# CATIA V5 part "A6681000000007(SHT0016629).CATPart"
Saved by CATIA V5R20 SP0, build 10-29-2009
Part number: A668100000007(SHT0016629)
Source: Unknown
Bounding box of the stored display mesh (mm): x -453 to 31, y 582 to 876, z 0.9 to 38.4
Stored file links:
  E:\杨逍\02-飞秋\冉凡勇\2023-10-08 13_49_22\2D\副驾\宽车副驾底支架\A668100000007（SHT0016629）-A6宽车副司机座椅底支架总成\A6681000000007(SHT0016629).CATPart

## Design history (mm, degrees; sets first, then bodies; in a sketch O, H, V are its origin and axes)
Set1
  Point1: type OnCurve, Support edge [face of Solid1 | face of Solid1], Ratio 0.5
  Plane1: type Normal, Curve edge [face of Solid1 | face of Solid1], RefPoint Point1
Body1 "SHT0016382-A6宽车副司机座椅底支架上板" (main body)
  Solid1: solid without history
Body2 "SHT0016383-A6宽车副司机座椅底支架左下板"
  Solid2: solid without history
  Translate1: ToTransfor Solid2, Direction face of Solid2, Length -91
Body3 "SHT0016384-A6宽车副司机座椅底支架右下板"
  Solid3: solid without history
  Translate2: ToTransfor Solid3, Direction face of Solid3, Length -91
Body4 "Q37108-焊接方螺母"
  Solid4: solid without history
Body5 "Q37108-焊接方螺母"
  Solid5: solid without history
Body6 "Q37108-焊接方螺母"
  Solid6: solid without history
Body7 "Q37108-焊接方螺母"
  Solid7: solid without history
Body8 "Q37108-焊接方螺母"
  Solid8: solid without history
Body9 "Q37108-焊接方螺母"
  Solid9: solid without history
